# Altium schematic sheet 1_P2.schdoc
size 431 x 309 mm
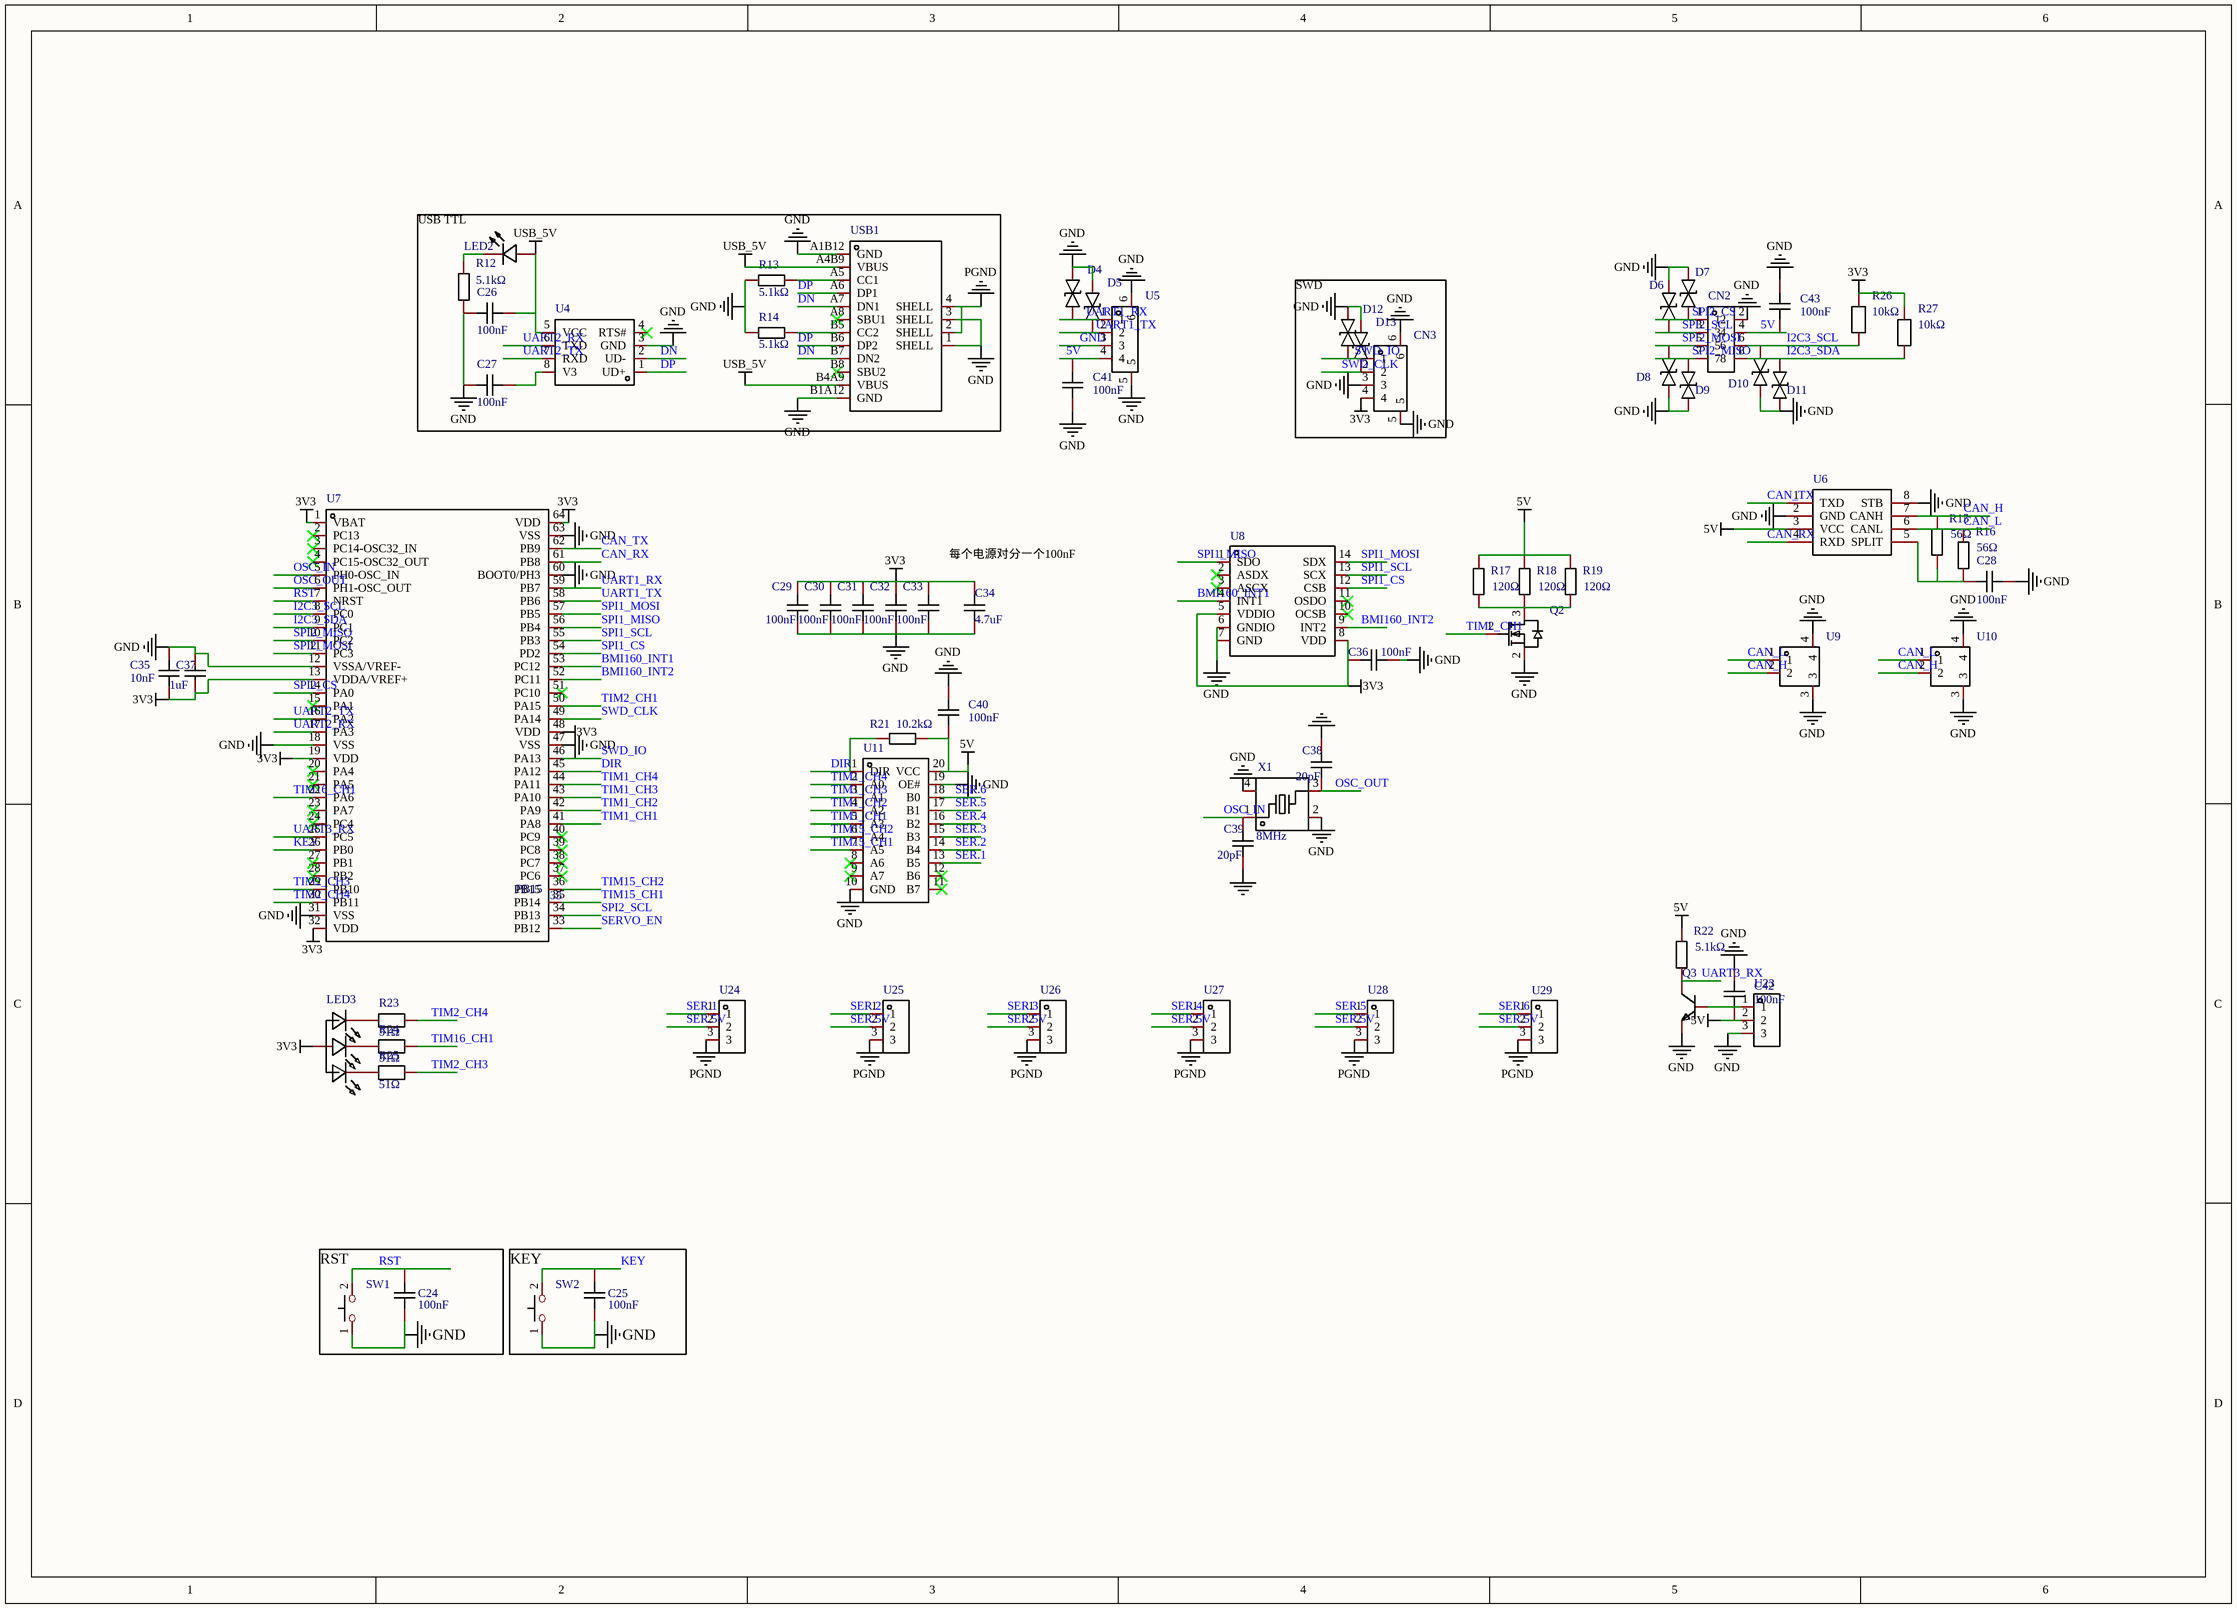
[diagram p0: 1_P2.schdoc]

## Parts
C24  Name: 100nF  [C0603]  (hidden comment: 1uF)
C25  Name: 100nF  [C0603]  (hidden comment: 1uF)
C26  value 100nF  [C0603]  (hidden comment: TCC0603X7R104K500CT)
C27  value 100nF  [C0603]  (hidden comment: TCC0603X7R104K500CT)
C28  value 100nF  [C0603]  (hidden comment: CL10B104KC8NNNC)
C29  value 100nF  [C0402]  (hidden comment: GCM155R71C104KA55J)
C30  value 100nF  [C0402]  (hidden comment: GCM155R71C104KA55J)
C31  value 100nF  [C0402]  (hidden comment: GCM155R71C104KA55J)
C32  value 100nF  [C0402]  (hidden comment: GCM155R71C104KA55J)
C33  value 100nF  [C0402]  (hidden comment: GCM155R71C104KA55J)
C34  value 4.7uF  [C0603]  (hidden comment: GRM188C81E475KE11D)
C35  value 10nF  [C0603]  (hidden comment: C0603C103K1RACAUTO)
C36  value 100nF  [C0402]  (hidden comment: GCM155R71C104KA55J)
C37  value 1uF  [C0603]  (hidden comment: 0603F105M160NT)
C38  value 20pF  [C0603]  (hidden comment: 0603CG200G500NT)
C39  value 20pF  [C0603]  (hidden comment: 0603CG200G500NT)
C40  value 100nF  [C0402]  (hidden comment: GCM155R71C104KA55J)
C41  value 100nF  [C0402]  (hidden comment: GCM155R71C104KA55J)
C42  value 100nF  [C0402]  (hidden comment: GCM155R71C104KA55J)
C43  value 100nF  [C0402]  (hidden comment: GCM155R71C104KA55J)
CN2  3110-08SG0BK00A1  [IDC-TH_3110-08SG0BK00A1]  (value not drawn)
CN3  X9821WVS-04-9TSN  [CONN-SMD_4P-P1.25_X9821WVS-04-9TSN]  (value not drawn)
D4  PESD5V0L1BA  [SOD-323_L1.7-W1.3-LS2.5-BI]  (value not drawn)
D5  PESD5V0L1BA  [SOD-323_L1.7-W1.3-LS2.5-BI]  (value not drawn)
D6  PESD5V0L1BA  [SOD-323_L1.7-W1.3-LS2.5-BI]  (value not drawn)
D7  PESD5V0L1BA  [SOD-323_L1.7-W1.3-LS2.5-BI]  (value not drawn)
D8  PESD5V0L1BA  [SOD-323_L1.7-W1.3-LS2.5-BI]  (value not drawn)
D9  PESD5V0L1BA  [SOD-323_L1.7-W1.3-LS2.5-BI]  (value not drawn)
D10  PESD5V0L1BA  [SOD-323_L1.7-W1.3-LS2.5-BI]  (value not drawn)
D11  PESD5V0L1BA  [SOD-323_L1.7-W1.3-LS2.5-BI]  (value not drawn)
D12  PESD5V0L1BA  [SOD-323_L1.7-W1.3-LS2.5-BI]  (value not drawn)
D13  PESD5V0L1BA  [SOD-323_L1.7-W1.3-LS2.5-BI]  (value not drawn)
LED2  NCD0805R1  [LED0805-RD_RED]  (value not drawn)
LED3  HL-PCF-3216S39FU70GH203BC-A  [LED-SMD_4P-L3.2-W1.5-BL]  (value not drawn)
Q2  AO3400  [SOT-23_L2.9-W1.3-P1.90-LS2.4-BR]  (value not drawn)
Q3  PMBT3904,235  [SOT-23-3_L2.9-W1.3-P1.90-LS2.3-BR-1]  (value not drawn)
R12  value 5.1kΩ  [R0603]  (hidden comment: RMC06035.1K5%N)
R13  value 5.1kΩ  [R0603]  (hidden comment: RMC06035.1K1%N)
R14  value 5.1kΩ  [R0603]  (hidden comment: RMC06035.1K1%N)
R15  value 56Ω  [R0603]  (hidden comment: CR0603JA0560G)
R16  value 56Ω  [R0603]  (hidden comment: CR0603JA0560G)
R17  value 120Ω  [R0603]  (hidden comment: RTT03121JTP)
R18  value 120Ω  [R0603]  (hidden comment: RTT03121JTP)
R19  value 120Ω  [R0603]  (hidden comment: RTT03121JTP)
R21  value 10.2kΩ  [R0603]  (hidden comment: 0603WAF1022T5E)
R22  value 5.1kΩ  [R0603]  (hidden comment: RS-03K512JT)
R23  value 51Ω  [R0603]  (hidden comment: ACPP0603 51R B)
R24  value 51Ω  [R0603]  (hidden comment: ACPP0603 51R B)
R25  value 51Ω  [R0603]  (hidden comment: ACPP0603 51R B)
R26  value 10kΩ  [R0603]  (hidden comment: SG73P1JTTD1002F)
R27  value 10kΩ  [R0603]  (hidden comment: SG73P1JTTD1002F)
SW1  YD-3410  [SW-SMD_L3.9-W2.9-LS4.8-EH-A]  (value not drawn)
SW2  YD-3410  [SW-SMD_L3.9-W2.9-LS4.8-EH-A]  (value not drawn)
U4  CH340N  [SOP-8_L4.9-W3.9-P1.27-LS6.0-BL]  (value not drawn)
U5  1.25-4PWTDK  [CONN-SMD_4P-P1.25_SHOUHAN_1.25-4PWTDK]  (value not drawn)
U6  TJA1040T/CM,118  [SOIC-8_L5.0-W4.0-P1.27-LS6.0-BL]  (value not drawn)
U7  NAME: PB15  NUMBER: 35  [LQFP-64_L10.0-W10.0-P0.50-LS12.0-BL]  (hidden comment: STM32L431RCT6)
U8  BMI160  [LGA-14_L3.0-W2.5-P0.50-BL]  (value not drawn)
U9  1.25-2PWTDK  [CONN-SMD_2P-P1.25_SHOU_1.25-2PWTDK]  (value not drawn)
U10  1.25-2PWTDK  [CONN-SMD_2P-P1.25_SHOU_1.25-2PWTDK]  (value not drawn)
U11  74HC245PW  [TSSOP-20_L6.5-W4.4-P0.65-LS6.4-BL]  (value not drawn)
U23  双塑直脚单排针 3p 19mm  [HDR-TH_3P-P2.54-V-M_C9900004029]  (value not drawn)
U24  双塑直脚单排针 3p 19mm  [HDR-TH_3P-P2.54-V-M_C9900004029]  (value not drawn)
U25  双塑直脚单排针 3p 19mm  [HDR-TH_3P-P2.54-V-M_C9900004029]  (value not drawn)
U26  双塑直脚单排针 3p 19mm  [HDR-TH_3P-P2.54-V-M_C9900004029]  (value not drawn)
U27  双塑直脚单排针 3p 19mm  [HDR-TH_3P-P2.54-V-M_C9900004029]  (value not drawn)
U28  双塑直脚单排针 3p 19mm  [HDR-TH_3P-P2.54-V-M_C9900004029]  (value not drawn)
U29  双塑直脚单排针 3p 19mm  [HDR-TH_3P-P2.54-V-M_C9900004029]  (value not drawn)
USB1  TYPE-C 16PIN 3MD(385)  [USB-C-SMD_TYPE-C16PIN]  (value not drawn)
X1  value 8MHz  [OSC-SMD_4P-L3.2-W2.5-BL]  (hidden comment: X32258MOB4SI)

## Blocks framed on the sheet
USB TTL: C26 C27 LED2 R12-R14 U4 USB1
SWD: CN3 D12 D13
RST: C24 SW1
KEY: C25 SW2

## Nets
3V3: C29.2 C30.2 C31.2 C32.2 C33.2 C34.2 C35.2 C36.1 C37.1 CN3.4 LED3.2 R26.2 R27.2 U7.1(VBAT) U7.13(VDDA/VREF+) U7.19(VDD) U7.32(VDD) U7.48(VDD) U7.64(VDD) U8.5(VDDIO) U8.8(VDD)
5V: C40.2 C41.1 C42.2 C43.2 CN2.4 R17.2 R18.2 R19.2 R21.2 R22.2 U5.4 U6.3(VCC) U11.20(VCC) U23.2
GND: C24.1 C25.1 C26.1 C27.1 C28.2 C29.1 C30.1 C31.1 C32.1 C33.1 C34.1 C35.1 C36.2 C37.2 C38.1 C39.2 C40.1 C41.2 C42.1 C43.1 CN2.2 CN3.3 CN3.5 CN3.6 D4.2 D5.2 D6.2 D7.2 D8.1 D9.1 D10.1 D11.1 D12.2 D13.2 Q2.2(S) Q3.2 R12.1 R13.1 R14.1 SW1.1 SW2.1 U4.3(GND) U5.3 U5.5 U5.6 U6.2(GND) U6.8(STB) U7.12(VSSA/VREF-) U7.18(VSS) U7.31(VSS) U7.47(VSS) U7.60(BOOT0/PH3) U7.63(VSS) U8.6(GNDIO) U8.7(GND) U9.3 U9.4 U10.3 U10.4 U11.10(GND) U11.19(OE#) U23.3 USB1.1(SHELL) USB1.3(SHELL) USB1.A1B12(GND) USB1.B1A12(GND) X1.2(GND) X1.4(GND)
PGND: U24.3 U25.3 U26.3 U27.3 U28.3 U29.3 USB1.2(SHELL) USB1.4(SHELL)
USB_5V: C26.2 LED2.2(+) U4.5(VCC) USB1.A4B9(VBUS) USB1.B4A9(VBUS)
BMI160_INT1: U7.53(PC12) U8.4(INT1)
BMI160_INT2: U7.52(PC11) U8.9(INT2)
CAN_H: R15.2 U6.7(CANH) U9.2 U10.2
CAN_L: R16.2 U6.6(CANL) U9.1 U10.1
CAN_RX: U6.4(RXD) U7.61(PB8)
CAN_TX: U6.1(TXD) U7.62(PB9)
DIR: R21.1 U7.45(PA12) U11.1(DIR)
DN: U4.2(UD-) USB1.A7(DN1) USB1.B7(DN2)
DP: U4.1(UD+) USB1.A6(DP1) USB1.B6(DP2)
I2C3_SCL: CN2.6 D10.2 R26.1 U7.8(PC0)
I2C3_SDA: CN2.8 D11.2 R27.1 U7.9(PC1)
KEY: C25.2 SW2.2 U7.26(PB0)
OSC_IN: C39.1 U7.5(PH0-OSC_IN) X1.1
OSC_OUT: C38.2 U7.6(PH1-OSC_OUT) X1.3
RST: C24.2 SW1.2 U7.7(NRST)
SER.1: U11.13(B5) U24.1
SER.2: U11.14(B4) U25.1
SER.3: U11.15(B3) U26.1
SER.4: U11.16(B2) U27.1
SER.5: U11.17(B1) U28.1
SER.5V: U24.2 U25.2 U26.2 U27.2 U28.2 U29.2
SER.6: U11.18(B0) U29.1
SERVO_EN: U7.33(PB12)
SPI1_CS: U7.54(PD2) U8.12(CSB)
SPI1_MISO: U7.56(PB4) U8.1(SDO)
SPI1_MOSI: U7.57(PB5) U8.14(SDX)
SPI1_SCL: U7.55(PB3) U8.13(SCX)
SPI2_CS: CN2.1 D7.1 U7.14(PA0)
SPI2_MISO: CN2.7 D9.2 U7.10(PC2)
SPI2_MOSI: CN2.5 D8.2 U7.11(PC3)
SPI2_SCL: CN2.3 D6.1 U7.34(PB13)
SWD_CLK: CN3.2 D13.1 U7.49(PA14)
SWD_IO: CN3.1 D12.1 U7.46(PA13)
TIM1_CH1: U7.41(PA8) U11.5(A3)
TIM1_CH2: U7.42(PA9) U11.4(A2)
TIM1_CH3: U7.43(PA10) U11.3(A1)
TIM1_CH4: U7.44(PA11) U11.2(A0)
TIM2_CH1: Q2.1(G) U7.50(PA15)
TIM2_CH3: R25.2 U7.29(PB10)
TIM2_CH4: R23.2 U7.30(PB11)
TIM15_CH1: U7.35(PB14) U11.7(A5)
TIM15_CH2: U7.36(PB15) U11.6(A4)
TIM16_CH1: R24.2 U7.22(PA6)
UART1_RX: D4.1 U5.1 U7.59(PB7)
UART1_TX: D5.1 U5.2 U7.58(PB6)
UART2_RX: U4.6(TXD) U7.17(PA3)
UART2_TX: U4.7(RXD) U7.16(PA2)
UART3_RX: Q3.3 R22.1 U7.25(PC5)
NetC27_2: C27.2 U4.8(V3)
NetC28_1: C28.1 R15.1 R16.1 U6.5(SPLIT)
NetLED2_1: LED2.1(-) R12.2
NetLED3_1: LED3.1 R23.1
NetLED3_3: LED3.3 R24.1
NetLED3_4: LED3.4 R25.1
NetQ2_3: Q2.3(D) R17.1 R18.1 R19.1
NetQ3_1: Q3.1 U23.1
NetR13_2: R13.2 USB1.A5(CC1)
NetR14_2: R14.2 USB1.B5(CC2)

Not connected (* = marked no-connect by the designer): U4 4(RTS#)*; U7 2(PC13)* 3(PC14-OSC32_IN)* 4(PC15-OSC32_OUT)* 15(PA1)* 20(PA4)* 21(PA5)* 23(PA7)* 24(PC4)* 27(PB1)* 28(PB2)* 37(PC6)* 38(PC7)* 39(PC8)* 40(PC9)* 51(PC10)*; U8 2(ASDX)* 3(ASCX)* 10(OCSB)* 11(OSDO)*; U11 8(A6)* 9(A7)* 11(B7)* 12(B6)*; USB1 A8(SBU1)* B8(SBU2)*

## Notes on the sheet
- 每个电源对分一个100nF

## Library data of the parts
C24 C25 = 1uF: Manufacturer: YAGEO; Manufacturer Part: CC0603JRNPO0BN200; Convert to PCB: yes
C26 C27 = TCC0603X7R104K500CT: 容值:100nF;精度:±10%;额定电压:50V;温度系数:X7R;; Manufacturer: CCTC(三环); Add into BOM: yes; Tolerance: ±10%; Voltage Rated: 50V; Temperature Coefficient: X7R
C28 = CL10B104KC8NNNC: 容值:100nF;精度:±10%;额定电压:100V;温度系数:X7R;; Manufacturer: SAMSUNG(三星); Add into BOM: yes; Tolerance: ±10%; Voltage Rated: 100V; Temperature Coefficient: X7R
C29-C33 C36 C40-C43 = GCM155R71C104KA55J: 容值:100nF;精度:±10%;额定电压:-;材质(温度系数):-;; Manufacturer: muRata(村田); Add into BOM: yes; Tolerance: ±10%
C34 = GRM188C81E475KE11D: 容值:4.7uF;精度:±10%;额定电压:-;温度系数:-;; Manufacturer: muRata(村田); Add into BOM: yes; Tolerance: ±10%
C35 = C0603C103K1RACAUTO: 温度系数:X7R;精度:±10%;额定电压:100V;容值:10nF;; Manufacturer: KEMET(基美); Add into BOM: yes; Temperature Coefficient: X7R; Tolerance: ±10%; Voltage Rated: 100V
C37 = 0603F105M160NT: 容值:1uF;精度:±20%;额定电压:16V;材质(温度系数):Y5V;; Manufacturer: FH(风华); Add into BOM: yes; Tolerance: ±20%; Voltage Rated: 16V; Temperature Coefficient: Y5V
C38 C39 = 0603CG200G500NT: 容值:20pF;精度:±2%;额定电压:50V;温度系数:C0G;; Manufacturer: FH(风华); Add into BOM: yes; Tolerance: ±2%; Voltage Rated: 50V; Temperature Coefficient: C0G
CN2 = 3110-08SG0BK00A1: 连接器类型:简牛座;间距:2.54mm;每排PIN数:4;排数:2;行距:2.54mm;封装形式:直插;触头材质:黄铜;触头镀层:金;; Manufacturer: Wcon(维峰电子); Add into BOM: yes; Connector Type: 简牛座; Pitch: 2.54mm; Pin Number in each Row: 4; Holder Type: 直插
CN3 = X9821WVS-04-9TSN: 参考系列:-;间距:1.25mm;插针结构:1x4P;排数:1;每排PIN数:4;行距:-;安装方式:-;触头材质:黄铜;; Manufacturer: XKB Connectivity(中国星坤); Add into BOM: yes; Pitch: 1.25mm; Pins Structure: 1x4P; Number of PINs Per Row: 4
D4-D13 = PESD5V0L1BA: 极性:-;反向关断电压（典型值）:-;击穿电压（最小值）:-;箝位电压:-;峰值脉冲电流（10/1000us）:-;; Manufacturer: TECH PUBLIC(台舟); Symbol: PESD5V0L1BA_C2827691; Add into BOM: yes
LED2 = NCD0805R1: 发光颜色:红灯;; Manufacturer: 国星光电; Symbol: FC-2012HRK-620D; Add into BOM: yes; Emitted Color: 红灯
LED3 = HL-PCF-3216S39FU70GH203BC-A: 发光颜色:RGB三色;透镜颜色:无色透明;主波长:-;色温:-;光通量(25时):-;测试电流:20mA;正向电压(VF):2.4V；3.4V；3.4V;发光强度:350mcd；1000mcd；220mcd;功率:102mW；102mW；72mW;发光角度:140°;安装方式:正贴;工作温度:-40~+85;; Manufacturer: HONGLITRONIC(鸿利光电); Add into BOM: yes; Emitted Color: RGB三色; Lens Color: 无色透明; Forward Current: 20mA; Viewing Angle: 140°; Mounting Sytle: 正贴
Q2 = AO3400: 类型:N沟道;漏源电压(Vdss):30V;连续漏极电流(Id):5.8A;功率(Pd):1.5W;导通电阻(RDS(on)@Vgs,Id):35mΩ@10V,5.8A;阈值电压(Vgs(th)@Id):1.2V@250uA;栅极电荷(Qg@Vgs):-;输入电容(Ciss@Vds):1050pF@15V;反向传输电容(Crss@Vds):77pF@15V;工作温度:+150@(Tj);; Manufacturer: GOODWORK(固得沃克); Symbol: AO3400_C2938367; Add into BOM: yes; Type: N沟道; Drain Source Voltage (Vdss): 30V; Power Dissipation (Pd): 1.5W
Q3 = PMBT3904,235: 晶体管类型:NPN;集射极击穿电压(Vceo):40V;集电极电流(Ic):200mA;功率(Pd):250mW;集电极截止电流(Icbo):50nA;集电极-发射极饱和电压(VCE(sat)@Ic,Ib):300mV@50mA,5mA;直流电流增益(hFE@Ic,Vce):100@10mA,1V;特征频率(fT):300MHz;工作温度:+150@(Tj);; Manufacturer: Nexperia(安世); Add into BOM: yes; Transistor Type: NPN; Collector-Emitter Breakdown Voltage (Vceo): 40V; Collector Current (Ic): 200mA; Power Dissipation (Pd): 250mW; Collector Cut-Off Current (Icbo): 50nA; Transition Frequency (fT): 300MHz
R12 = RMC06035.1K5%N: 阻值:5.1kΩ;精度:±5%;功率:0.1W;; Manufacturer: Tyohm(幸亚电阻); Add into BOM: yes; Tolerance: ±5%; Power(Watts): 0.1W
R13 R14 = RMC06035.1K1%N: 阻值:5.1kΩ;精度:±1%;功率:0.1W;; Manufacturer: Tyohm(幸亚电阻); Add into BOM: yes; Tolerance: ±1%; Power(Watts): 0.1W
R15 R16 = CR0603JA0560G: 电阻类型:厚膜电阻;阻值:56Ω;精度:±5%;功率:1/10W;温度系数:±200ppm/;最大工作电压:50V;工作温度范围:-55~+125;; Manufacturer: LIZ(丽智电子); Add into BOM: yes; Tolerance: ±5%; Power(Watts): 1/10W; Overload Voltage (Max): 50V
R17-R19 = RTT03121JTP: 电阻类型:厚膜电阻;阻值:120Ω;精度:±5%;功率:1/10W;温度系数:±100ppm/;最大工作电压:75V;工作温度范围:-55~+155;; Manufacturer: RALEC(旺诠); Add into BOM: yes; Tolerance: ±5%; Power(Watts): 1/10W; Overload Voltage (Max): 75V
R21 = 0603WAF1022T5E: 电阻类型:厚膜电阻;阻值:10.2kΩ;精度:±1%;功率:1/10W;温度系数:±100ppm/;最大工作电压:75V;工作温度范围:-55~+155;; Manufacturer: UNI-ROYAL(厚声); Add into BOM: yes; Tolerance: ±1%; Power(Watts): 100mW; Overload Voltage (Max): 75V
R22 = RS-03K512JT: 阻值:5.1kΩ;精度:±5%;功率:100mW;温度系数:±100ppm/;最大工作电压:50V;工作温度范围:-55~+155;; Manufacturer: FH(风华); Add into BOM: yes; Tolerance: ±5%; Power(Watts): 100mW; Overload Voltage (Max): 50V
R23-R25 = ACPP0603 51R B: 电阻类型:薄膜电阻;阻值:51Ω;精度:±0.1%;功率:62.5mW;温度系数:-;最大工作电压:50V;工作温度范围:-55~+150;; Manufacturer: Ohmite; Add into BOM: yes; Tolerance: ±0.1%; Power(Watts): 62.5mW; Overload Voltage (Max): 50V
R26 R27 = SG73P1JTTD1002F: 阻值:10kΩ;精度:±1%;功率:-;; Manufacturer: KOA; Add into BOM: yes; Tolerance: ±1%
SW1 SW2 = YD-3410: Add into BOM: yes
U4 = CH340N: Manufacturer: WCH(南京沁恒); Symbol: CH340N_C2977777; Add into BOM: yes
U5 = 1.25-4PWTDK: 间距:1.25mm;插针结构:1x4P;排数:1;每排PIN数:4;公母:公型插针;安装方式:卧贴;额定电流:1A;工作温度范围:-25~+85;; Manufacturer: SHOU HAN(首韩); Add into BOM: yes; Pitch: 1.25mm; Pins Structure: 1x4P; Number of PINs Per Row: 4; Gender: 公型插针; Current Rating (Max): 1A
U6 = TJA1040T/CM,118: 类型:收发器;协议类别:CAN总线;; Manufacturer: NXP(恩智浦); Add into BOM: yes; Protocol: CAN总线; Supply Voltage: 4.75V ~ 5.25V
U7 = STM32L431RCT6: 主频（MAX):80MHz;工作电压:1.71V ~ 3.6V;; Manufacturer: ST(意法半导体); Add into BOM: yes; Speed: 80MHz; Program Memory Size: 256KB; RAM Size: 64KB; Number of I/O: 52; A/D: 16x12bit; D/A: 2x12bit; PWM: 1; UART/USART: 3 USART+1 UART; SPI: 3
U8 = BMI160: 低功率惯性测量装置; Manufacturer: Bosch(博世); Add into BOM: yes
U9 U10 = 1.25-2PWTDK: 间距:1.25mm;插针结构:1x2P;排数:1;每排PIN数:2;公母:公型插针;安装方式:卧贴;额定电流:1A;工作温度范围:-25~+85;; Manufacturer: SHOU HAN(首韩); Add into BOM: yes; Pitch: 1.25mm; Pins Structure: 1x2P; Number of PINs Per Row: 2; Gender: 公型插针; Current Rating (Max): 1A
U11 = 74HC245PW: 逻辑电路的归属系列:-;逻辑类型:-;元件数:-;每元件位数:-;; Add into BOM: yes
U23-U29 = 双塑直脚单排针 3p 19mm: Symbol: 3P-19MM; Add into BOM: yes
USB1 = TYPE-C 16PIN 3MD(385): 连接器类型:Type-C;标准:-;公母:母座;触点数量:16;端口数量:1;安装方式:卧贴;额定电流 - 电源:3A;工作温度范围:-40~+85;; Manufacturer: SHOU HAN(首韩); Add into BOM: yes; Gender: 母座; Number of Contacts: 16; Number of Ports: 1; Current Rating - Power (Max): 3A
X1 = X32258MOB4SI: 晶振类型:贴片无源晶振;频率:8MHz;频率公差:±10ppm;频率稳定度:±30ppm;负载电容:12pF;工作温度:-40~+85;; Manufacturer: YXC扬兴科技; Add into BOM: yes; Crystal Type: 贴片无源晶振; Frequency Tolerance: ±10ppm; Frequency Stability: ±30ppm; Load Capacitance: 12pF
